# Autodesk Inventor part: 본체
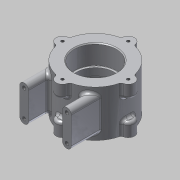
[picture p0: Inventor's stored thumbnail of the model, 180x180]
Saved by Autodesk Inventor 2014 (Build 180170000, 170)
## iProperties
Created: 2015-03
Part Number: 본체
Material: 알루미늄 6061
Document SubType Name: Modeling
Designer: Administrator
Density: 2.71 g/cm^3
Appearance: 알루미늄 - 평지
Mass: 450.776 g
Surface Area: 332.745 cm^2
Volume: 166.338 cm^3
Author: Administrator
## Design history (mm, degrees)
sketch "스케치1"
  geometry: C1 r 37 at (0, 0); 1 further point
  constraints: 1 centre point, 1 coincident
  dimensions: "d0" = 74 diameter of C1
extrude "돌출1" new body sketch "스케치1" stored distance "d1" = 52; taper "d2" = 0 deg
sketch "스케치2"
  geometry: C1 r 37 at (0, 0) reference; C2 r 23.5 at (0, 0)
  constraints: 1 centre point, 1 coincident
  dimensions: "d5" = 47 diameter of C2
extrude "돌출2" cut sketch "스케치2" distance "d6" = 22; taper "d7" = 0 deg
sketch "스케치3"
  geometry: C1 r 23.5 at (0, 0) reference; C2 r 21 at (0, 0)
  constraints: 1 centre point, 1 coincident
  dimensions: "d8" = 42 diameter of C2
extrude "돌출3" cut sketch "스케치3" distance "d9" = 8; taper "d10" = 0 deg
sketch "스케치4"
  geometry: C1 r 37 at (0, 0) reference; C2 r 23.5 at (0, 0)
  constraints: 1 centre point, 1 coincident
  dimensions: "d11" = 47 diameter of C2
extrude "돌출4" cut sketch "스케치4" distance "d12" = 22; taper "d13" = 0 deg
sketch "스케치5"
  geometry: C1 r 23.5 at (0, 0) reference; C2 r 7 at (0, 37); C3 r 7 at (-37, 0); C4 r 7 at (0, -37); C5 r 7 at (37, 0); A1 r 37 centre (0, 0) between (0, 37) and (-37, 0) reference
  constraints: 4 centre point, 4 point on circle, 2 horizontal alignment, 2 vertical alignment
  dimensions: "d15" = 7 radius of C2; "d16" = 7 radius of C3; "d17" = 7 radius of C4; "d18" = 7 radius of C5
extrude "돌출5" join sketch "스케치5" distance "d19" = 15; taper "d20" = 0 deg
sketch "스케치6"
  geometry: A1 r 7 centre (0, 37) between (6.969, 36.338) and (-6.969, 36.338) reference; A2 r 7 centre (-37, 0) between (-36.338, 6.969) and (-36.338, -6.969) reference; A3 r 7 centre (0, -37) between (-6.969, -36.338) and (6.969, -36.338) reference; A4 r 7 centre (37, 0) between (36.338, -6.969) and (36.338, 6.969) reference; 4 further points
  constraints: 4 coincident
hole "구멍1" sketch "스케치6" at (0, 37), (-37, 0), (0, -37), (37, 0) diameter "d21" = 3.242; stored, may be unused: countersink angle "d25" = 90 deg, drill point angle "d27" = 118 deg; dims "d22" = 8, "d23" = 4, "d24" = 2, "d26" = 11
sketch "스케치7"
  geometry: L1 (-29, -22.978)-(-29, -56); L2 (-29, -56)-(-19, -56); L3 (-19, -56)-(-19, -31.749); L4 (19, -31.749)-(19, -56); L5 (19, -56)-(29, -56); L6 (29, -56)-(29, -22.978); A1 r 37 centre (0, 0) between (-36.338, -6.969) and (-6.969, -36.338) reference; A2 r 37 centre (0, 0) between (6.969, -36.338) and (36.338, -6.969) reference; 1 further point
  constraints: 12 end point, 4 point on circle, 3 parallel, 2 perpendicular, 1 collinear, 1 vertical
  dimensions: "d28" = 58 distance between parallel lines of L6 L1; "d29" = 56 distance from line of L5 point (0, 0); "d30" = 29 distance from line of point (0, 0) L1; "d31" = 10 distance between parallel lines of L3 L1; "d32" = 10 distance between parallel lines of L6 L4
extrude "돌출6" join sketch "스케치7" stored distance "d33" = 40; taper "d34" = 0 deg
fillet "모깎기1" dims "d35" = 5
sketch "스케치9"
  geometry: A1 r 5 centre (0, 0) between (-5, 0) and (5, 0) reference; A2 r 5 centre (0, 30) between (5, 30) and (-5, 30) reference; 3 further points
  constraints: 2 coincident
hole "구멍2" sketch "스케치9" at (0, 30), (0, 0) diameter "d36" = 4.134; stored, may be unused: countersink angle "d40" = 90 deg, drill point angle "d42" = 118 deg; dims "d37" = 6, "d38" = 4, "d39" = 2, "d41" = 8
sketch "스케치10"
  geometry: L1 (0, 0)-(-37, 0); L2 (0, 0)-(0, 37); L3 (0, 0)-(-26.163, 26.163); A1 r 37 centre (0, 0) between (-6.969, 36.338) and (-36.338, 6.969) reference; A2 r 37 centre (0, 0) between (-36.338, 6.969) and (-36.338, -6.969) reference; A3 r 37 centre (0, 0) between (6.969, 36.338) and (-6.969, 36.338) reference; 2 further points
  constraints: 6 end point, 3 point on circle, 1 coincident
  dimensions: "d44" = 45 deg angle of L1 L3
node "작업 평면1"
sketch "스케치11"
  geometry: L1 (-20.767, -26)-(20.767, -26) reference; 2 further points
  constraints: 1 coincident, 1 other
  dimensions: "d45" = 26 distance from line of point (0, 0) L1
feature "엠보싱1" sketch "스케치11" dims "d46" = 0.5, "d47" = 0
chamfer "모따기1" distance "d48" = 1; stored, may be unused: second distance "d49" = 2, angle "d50" = 45 deg
fillet "모깎기2" dims "d51" = 0.3
fillet "모깎기3" dims "d52" = 3
fillet "모깎기6" dims "d55" = 3
fillet "모깎기7" dims "d56" = 3
node "솔리드1"
mirror "대칭1"
mirror "대칭2"
